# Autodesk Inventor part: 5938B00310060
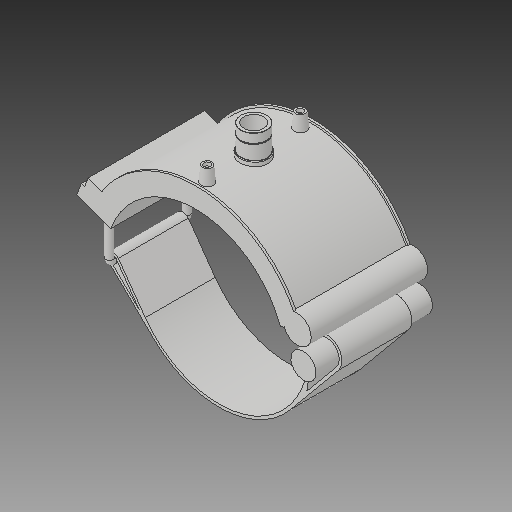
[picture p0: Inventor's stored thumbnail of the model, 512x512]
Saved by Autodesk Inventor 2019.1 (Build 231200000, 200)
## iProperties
Created: 2017-07
Part Number: 5938B00310060
Material: Generic
Description: PLASSON TRANSITION SADDLE 10''IPS x 1"NPT
Document SubType Name: Modeling
Designer: KIM
Density: 1 g/cm^3
Appearance: Default
Author: KIM
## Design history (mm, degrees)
derived "5938B.ipt"
feature "Solid1::5938B.ipt"
tag "TaggingFeature1"
body "Solid1"
other parameters: "d0" = 272.7, "d1" = 327.24, "d2" = 450.85, "d3" = 68.175, "d4" = 176.022, "d5" = 0, "d40" = 170.1648, "d41" = 42.4074, "d43" = 0, "d45" = 0, "d47" = 205.53, "d48" = 39.3783, "d50" = 0, "d78" = 185.62, "d79" = 15, "d80" = 70.4088, "d82" = 5 deg, "d84" = 4, "d85" = 14, "d86" = 0, "d87" = 3, "d88" = 0, "d96" = 333.7848, "d97" = 3.52044, "d98" = 0, "d102" = 0.90873, "d103" = 30.291, "d104" = 25.146, "d105" = 0, "d106" = 24.2328, "d108" = 0, "d109" = -13.97, "d111" = 0.5, "d112" = 0.5, "d113" = 0, "d114" = 0.5, "d117" = 0.30291, "d120" = 140 deg, "d121" = 24.228, "d122" = 20 deg, "d123" = 1308.96, "d124" = 196.344, "d126" = 0, "d143" = 280.881, "d145" = 41.95385, "d149" = 4.0905, "d150" = 46.14923, "d153" = 176.022, "d154" = 0, "d156" = 163.62, "d157" = 160 deg, "d159" = 10.908, "d161" = 4.0905, "d162" = 105.6132, "d163" = 0, "d164" = 136.35, "d167" = 27.27, "d168" = 159.62927, "d170" = 4.0905, "d172" = 0, "d173" = 1, "d175" = 136.35, "d176" = 20 deg, "d177" = 19.089, "d178" = 54.54, "d180" = 0, "d183" = 21.816, "d184" = 15.2712, "d185" = 57.20715, "d186" = 57.20715, "d187" = 163.62, "d188" = 16.362, "d189" = 19.089, "d190" = 0, "d191" = 196.344, "d193" = 10.908, "d194" = 5.59035, "d195" = 90 deg, "d197" = 0, "d199" = 0, "d_" = 272.7, "B_" = 180.34, "H_" = 41.91, "L_" = 176.022, "d_t" = 6, "G_" = 30.291, "d148" = 4.0905, "d160" = 4.0905, "d169" = 4.0905, "d192" = 10.908
